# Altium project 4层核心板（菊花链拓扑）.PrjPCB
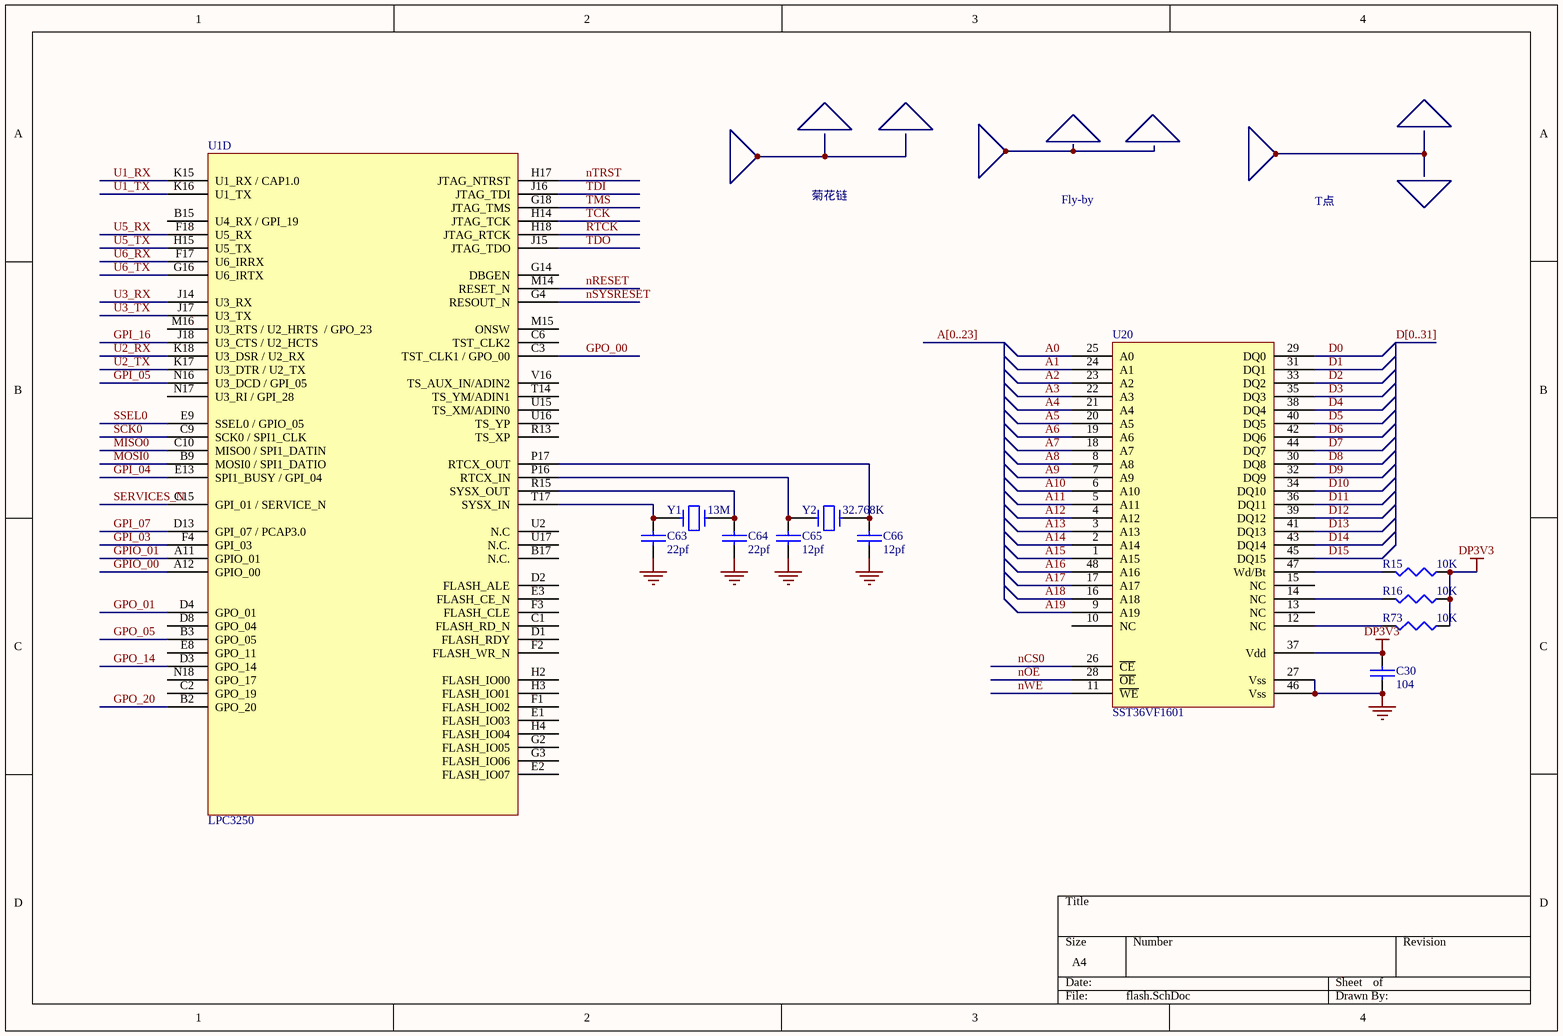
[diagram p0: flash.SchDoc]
6 sheets, 61 parts. Net scope: global (net labels, ports and power ports of the same name join across sheets).
Board file: Mian_CORE（完成版）.PcbDoc
Sheets:
  flash.SchDoc
  interface.SchDoc
  power.SchDoc
  sdram.SchDoc
  CPU.SchDoc
  EMC.SchDoc

## Sheet flash.SchDoc
size A4

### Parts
C30  104  [0603C]
C63  22pf  [0603C]
C64  22pf  [0603C]
C65  12pf  [0603C]
C66  12pf  [0603C]
R15  10K  [0603R]
R16  10K  [0603R]
R73  10K  [0603R]
U1  LPC3250  [TFBGA296]  (part D of 4)
U20  SST36VF1601  [TSOP-48]
Y1  13M  [XTAL-D]
Y2  32.768K  [XTAL-D]

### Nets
DP3V3: C30.1 R15.1 R16.1 R73.1 U20.37(Vdd)
GND: C30.2 C63.2 C64.2 C65.2 C66.2 U20.27(Vss) U20.46(Vss)
A0: U20.25(A0)
A1: U20.24(A1)
A2: U20.23(A2)
A3: U20.22(A3)
A4: U20.21(A4)
A5: U20.20(A5)
A6: U20.19(A6)
A7: U20.18(A7)
A8: U20.8(A8)
A9: U20.7(A9)
A10: U20.6(A10)
A11: U20.5(A11)
A12: U20.4(A12)
A13: U20.3(A13)
A14: U20.2(A14)
A15: U20.1(A15)
A16: U20.48(A16)
A17: U20.17(A17)
A18: U20.16(A18)
A19: U20.9(A19)
D0: U20.29(DQ0)
D1: U20.31(DQ1)
D2: U20.33(DQ2)
D3: U20.35(DQ3)
D4: U20.38(DQ4)
D5: U20.40(DQ5)
D6: U20.42(DQ6)
D7: U20.44(DQ7)
D8: U20.30(DQ8)
D9: U20.32(DQ9)
D10: U20.34(DQ10)
D11: U20.36(DQ11)
D12: U20.39(DQ12)
D13: U20.41(DQ13)
D14: U20.43(DQ14)
D15: U20.45(DQ15)
GPI_03: U1.F4(GPI_03)
GPI_04: U1.E13(SPI1_BUSY_/_GPI_04)
GPI_05: U1.N16(U3_DCD_/_GPI_05)
GPI_07: U1.D13(GPI_07_/_PCAP3.0)
GPI_16: U1.J18(U3_CTS_/_U2_HCTS)
GPIO_00: U1.A12(GPIO_00)
GPIO_01: U1.A11(GPIO_01)
GPO_00: U1.C3(TST_CLK1_/_GPO_00)
GPO_01: U1.D4(GPO_01)
GPO_05: U1.B3(GPO_05)
GPO_14: U1.D3(GPO_14)
GPO_20: U1.B2(GPO_20)
MISO0: U1.C10(MISO0_/_SPI1_DATIN)
MOSI0: U1.B9(MOSI0_/_SPI1_DATIO)
nCS0: U20.26(~{CE})
nOE: U20.28(~{OE})
nRESET: U1.M14(RESET_N)
nSYSRESET: U1.G4(RESOUT_N)
nTRST: U1.H17(JTAG_NTRST)
nWE: U20.11(~{WE})
RTCK: U1.H18(JTAG_RTCK)
SCK0: U1.C9(SCK0_/_SPI1_CLK)
SERVICES_N: U1.C15(GPI_01_/_SERVICE_N)
SSEL0: U1.E9(SSEL0_/_GPIO_05)
TCK: U1.H14(JTAG_TCK)
TDI: U1.J16(JTAG_TDI)
TDO: U1.J15(JTAG_TDO)
TMS: U1.G18(JTAG_TMS)
U1_RX: U1.K15(U1_RX_/_CAP1.0)
U1_TX: U1.K16(U1_TX)
U2_RX: U1.K18(U3_DSR_/_U2_RX)
U2_TX: U1.K17(U3_DTR_/_U2_TX)
U3_RX: U1.J14(U3_RX)
U3_TX: U1.J17(U3_TX)
U5_RX: U1.F18(U5_RX)
U5_TX: U1.H15(U5_TX)
U6_RX: U1.F17(U6_IRRX)
U6_TX: U1.G16(U6_IRTX)
NetC63_1: C63.1 U1.T17(SYSX_IN) Y1.2
NetC64_1: C64.1 U1.R15(SYSX_OUT) Y1.1
NetC65_1: C65.1 U1.P16(RTCX_IN) Y2.2
NetC66_1: C66.1 U1.P17(RTCX_OUT) Y2.1
NetR15_2: R15.2 U20.47(Wd/Bt)
NetR16_2: R16.2 U20.14(NC)
NetR73_2: R73.2 U20.12(NC)

Not connected (* = marked no-connect by the designer): U1 B15(U4_RX_/_GPI_19) B17(N.C.) C1(FLASH_RD_N) C2(GPO_19) C6(TST_CLK2) D1(FLASH_RDY) D2(FLASH_ALE) D8(GPO_04) E1(FLASH_IO03) E2(FLASH_IO07) E3(FLASH_CE_N) E8(GPO_11) F1(FLASH_IO02) F2(FLASH_WR_N) F3(FLASH_CLE) G2(FLASH_IO05) G3(FLASH_IO06) G14(DBGEN) H2(FLASH_IO00) H3(FLASH_IO01) H4(FLASH_IO04) M15(ONSW) M16(U3_RTS_/_U2_HRTS__/_GPO_23) N17(U3_RI_/_GPI_28) N18(GPO_17) R13(TS_XP) T14(TS_YM/ADIN1) U2(N.C) U15(TS_XM/ADIN0) U16(TS_YP) U17(N.C.) V16(TS_AUX_IN/ADIN2); U20 10(NC) 13(NC) 15(NC)

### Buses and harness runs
bus A[0..23]
bus D[0..31]

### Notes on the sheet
- 菊花链
- Fly-by
- T点

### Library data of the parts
C30 C63-C66 = CAP: Capacitor
R15 R16 R73 = RES
U1 = LPC3250A
Y1 Y2 = CRYSTAL

## Sheet interface.SchDoc
size A4
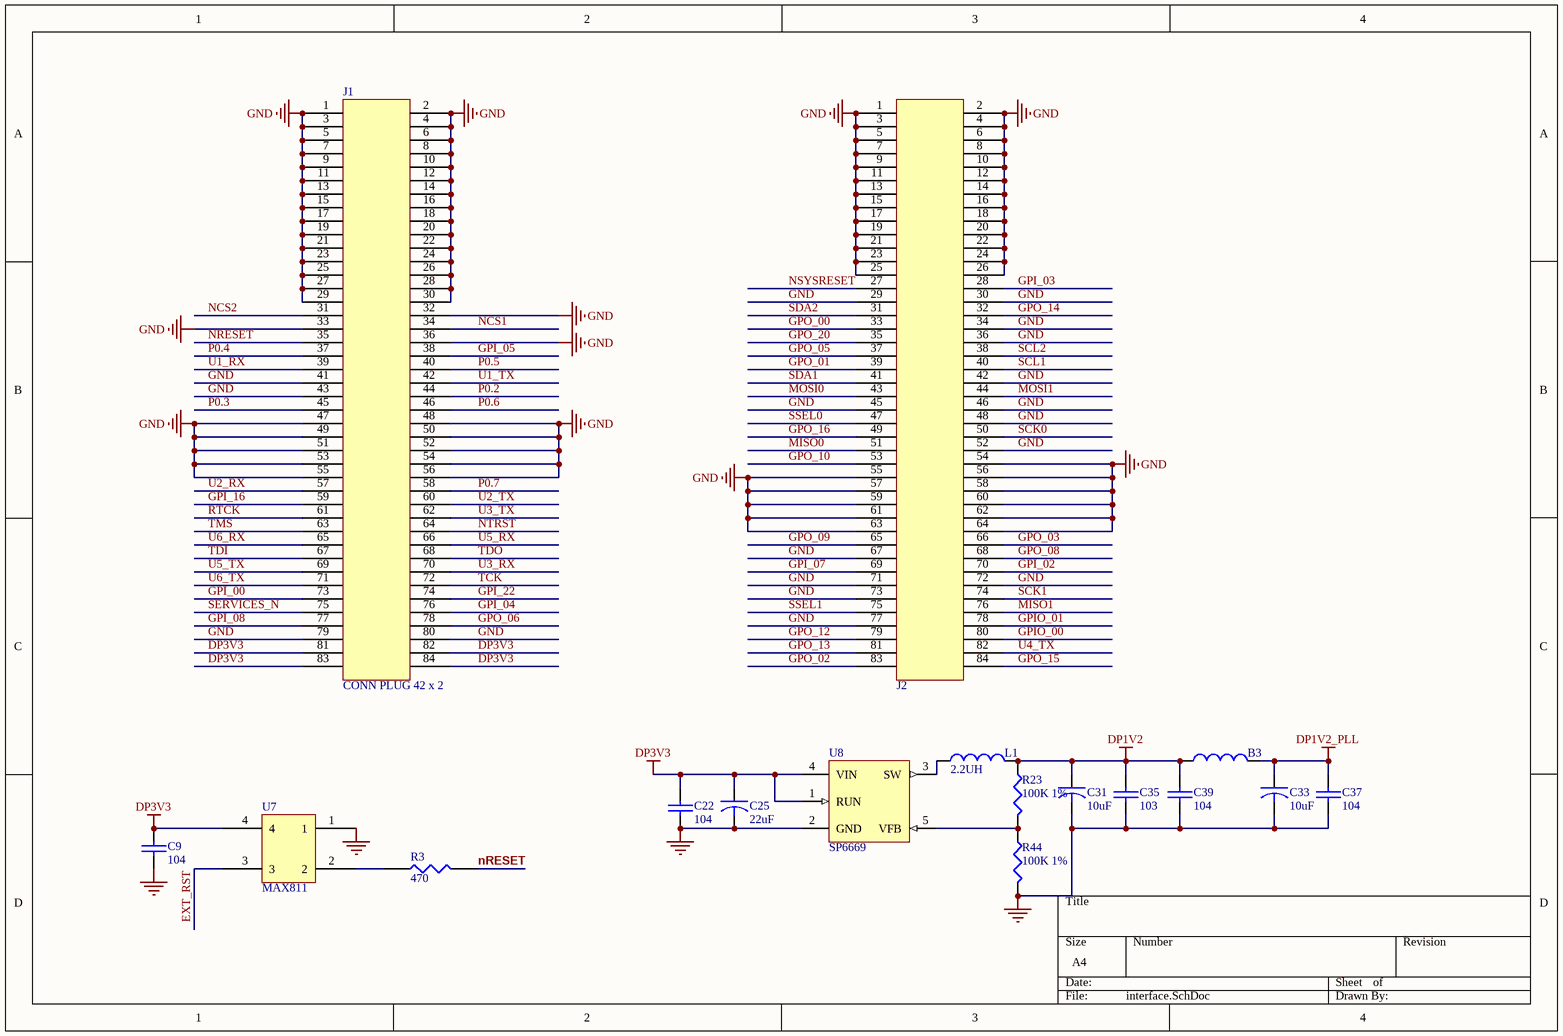
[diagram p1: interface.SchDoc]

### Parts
B3  (no value)  [0603]
C9  104  [0603C]
C22  104  [0603C]
C25  22uF  [TC-3528]
C31  10uF  [TC-3528]
C33  10uF  [TC-3528]
C35  103  [0603C]
C37  104  [0603C]
C39  104  [0603C]
J1  CONN PLUG 42 x 2  [DIP84]
J2  CONN PLUG 42 x 2  [DIP84]  (value not drawn)
L1  2.2UH  [0805]
R3  470  [0603R]
R23  100K 1%  [0603R]
R44  100K 1%  [0603R]
U7  MAX811  [MAX811]
U8  SP6669  [SOT-23-5]

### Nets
DP1V2: B3.1 C31.1 C35.2 C39.2 L1.2 R23.1
DP1V2_PLL: B3.2 C33.1 C37.2
DP3V3: C9.1 C22.2 C25.1 J1.81 J1.82 J1.83 J1.84 U7.4 U8.1(RUN) U8.4(VIN)
GND: C9.2 C22.1 C25.2 C31.2 C33.2 C35.1 C37.1 C39.1 J1.1 J1.2 J1.3 J1.4 J1.5 J1.6 J1.7 J1.8 J1.9 J1.10 J1.11 J1.12 J1.13 J1.14 J1.15 J1.16 J1.17 J1.18 J1.19 J1.20 J1.21 J1.22 J1.23 J1.24 J1.25 J1.26 J1.27 J1.28 J1.29 J1.30 J1.32 J1.33 J1.36 J1.41 J1.43 J1.47 J1.48 J1.49 J1.50 J1.51 J1.52 J1.53 J1.54 J1.55 J1.56 J1.79 J1.80 J2.1 J2.2 J2.3 J2.4 J2.5 J2.6 J2.7 J2.8 J2.9 J2.10 J2.11 J2.12 J2.13 J2.14 J2.15 J2.16 J2.17 J2.18 J2.19 J2.20 J2.21 J2.22 J2.23 J2.24 J2.25 J2.26 J2.29 J2.30 J2.34 J2.36 J2.42 J2.45 J2.46 J2.48 J2.52 J2.54 J2.55 J2.56 J2.57 J2.58 J2.59 J2.60 J2.61 J2.62 J2.63 J2.64 J2.67 J2.71 J2.72 J2.73 J2.77 R44.2 U7.1 U8.2(GND)
EXT_RST: U7.3
GPI_00: J1.73
GPI_02: J2.70
GPI_03: J2.28
GPI_04: J1.76
GPI_05: J1.38
GPI_07: J2.69
GPI_08: J1.77
GPI_16: J1.59
GPI_22: J1.74
GPIO_00: J2.80
GPIO_01: J2.78
GPO_00: J2.33
GPO_01: J2.39
GPO_02: J2.83
GPO_03: J2.66
GPO_05: J2.37
GPO_06: J1.78
GPO_08: J2.68
GPO_09: J2.65
GPO_10: J2.53
GPO_12: J2.79
GPO_13: J2.81
GPO_14: J2.32
GPO_15: J2.84
GPO_16: J2.49
GPO_20: J2.35
MISO0: J2.51
MISO1: J2.76
MOSI0: J2.43
MOSI1: J2.44
NCS1: J1.34
NCS2: J1.31
nRESET: J1.35 R3.2
nSYSRESET: J2.27
nTRST: J1.64
P0.2: J1.44
P0.3: J1.45
P0.4: J1.37
P0.5: J1.40
P0.6: J1.46
P0.7: J1.58
RTCK: J1.61
SCK0: J2.50
SCK1: J2.74
SCL1: J2.40
SCL2: J2.38
SDA1: J2.41
SDA2: J2.31
SERVICES_N: J1.75
SSEL0: J2.47
SSEL1: J2.75
TCK: J1.72
TDI: J1.67
TDO: J1.68
TMS: J1.63
U1_RX: J1.39
U1_TX: J1.42
U2_RX: J1.57
U2_TX: J1.60
U3_RX: J1.70
U3_TX: J1.62
U4_TX: J2.82
U5_RX: J1.66
U5_TX: J1.69
U6_RX: J1.65
U6_TX: J1.71
NetL1_1: L1.1 U8.3(SW)
NetR3_1: R3.1 U7.2
NetR23_2: R23.2 R44.1 U8.5(VFB)

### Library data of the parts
B3 L1 = INDUCTOR
C9 C22 C35 C37 C39 = CAP: Capacitor
C25 C31 C33 = CAPACITOR
R3 = RES1
R23 R44 = RES
U8 = SP6659

## Sheet power.SchDoc
size A4
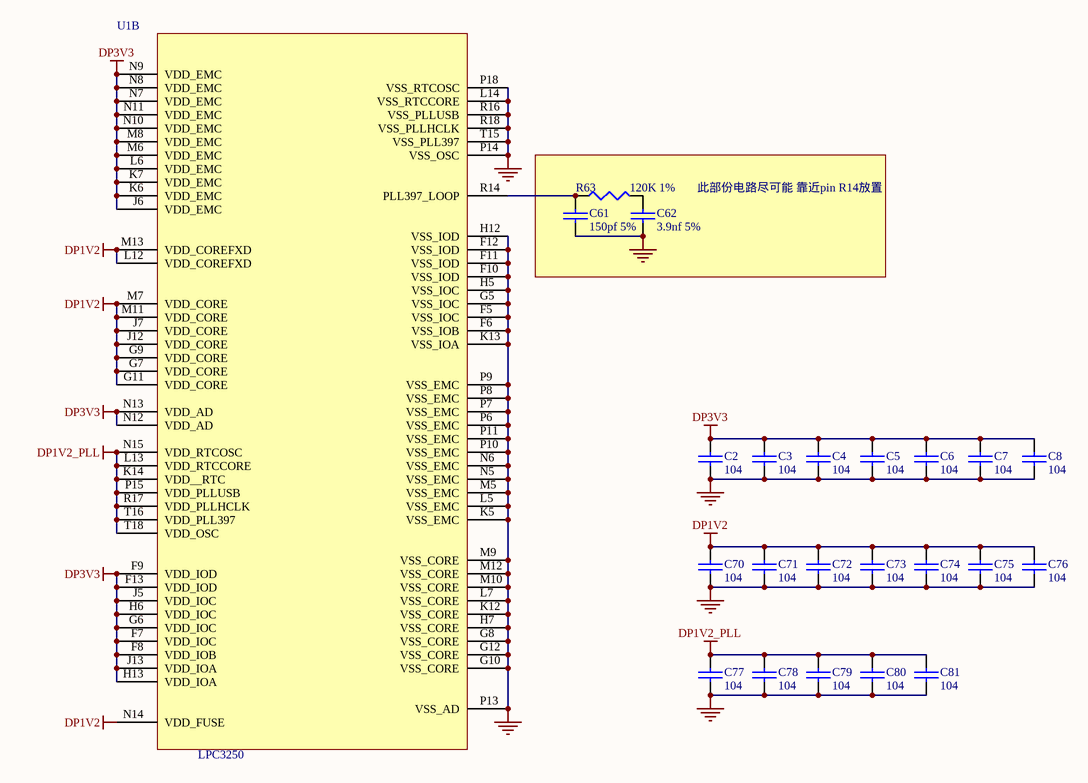
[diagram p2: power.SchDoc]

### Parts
C2  104  [0603C]
C3  104  [0603C]
C4  104  [0603C]
C5  104  [0603C]
C6  104  [0603C]
C7  104  [0603C]
C8  104  [0603C]
C61  150pf 5%  [0603C]
C62  3.9nf 5%  [0603C]
C70  104  [0603C]
C71  104  [0603C]
C72  104  [0603C]
C73  104  [0603C]
C74  104  [0603C]
C75  104  [0603C]
C76  104  [0603C]
C77  104  [0603C]
C78  104  [0603C]
C79  104  [0603C]
C80  104  [0603C]
C81  104  [0603C]
R63  120K 1%  [0603R]
U1  LPC3250  [TFBGA296]  (part B of 4)

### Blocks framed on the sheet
此部份电路尽可能 / 靠近pin R14放置: C61 C62 R63

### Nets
DP1V2: C70.1 C71.1 C72.1 C73.1 C74.1 C75.1 C76.1 U1.G7(VDD_CORE) U1.G9(VDD_CORE) U1.G11(VDD_CORE) U1.J7(VDD_CORE) U1.J12(VDD_CORE) U1.L12(VDD_COREFXD) U1.M7(VDD_CORE) U1.M11(VDD_CORE) U1.M13(VDD_COREFXD) U1.N14(VDD_FUSE)
DP1V2_PLL: C77.1 C78.1 C79.1 C80.1 C81.1 U1.K14(VDD__RTC) U1.L13(VDD_RTCCORE) U1.N15(VDD_RTCOSC) U1.P15(VDD_PLLUSB) U1.R17(VDD_PLLHCLK) U1.T16(VDD_PLL397) U1.T18(VDD_OSC)
DP3V3: C2.1 C3.1 C4.1 C5.1 C6.1 C7.1 C8.1 U1.F7(VDD_IOC) U1.F8(VDD_IOB) U1.F9(VDD_IOD) U1.F13(VDD_IOD) U1.G6(VDD_IOC) U1.H6(VDD_IOC) U1.H13(VDD_IOA) U1.J5(VDD_IOC) U1.J6(VDD_EMC) U1.J13(VDD_IOA) U1.K6(VDD_EMC) U1.K7(VDD_EMC) U1.L6(VDD_EMC) U1.M6(VDD_EMC) U1.M8(VDD_EMC) U1.N7(VDD_EMC) U1.N8(VDD_EMC) U1.N9(VDD_EMC) U1.N10(VDD_EMC) U1.N11(VDD_EMC) U1.N12(VDD_AD) U1.N13(VDD_AD)
GND: C2.2 C3.2 C4.2 C5.2 C6.2 C7.2 C8.2 C61.2 C62.2 C70.2 C71.2 C72.2 C73.2 C74.2 C75.2 C76.2 C77.2 C78.2 C79.2 C80.2 C81.2 U1.F5(VSS_IOC) U1.F6(VSS_IOB) U1.F10(VSS_IOD) U1.F11(VSS_IOD) U1.F12(VSS_IOD) U1.G5(VSS_IOC) U1.G8(VSS_CORE) U1.G10(VSS_CORE) U1.G12(VSS_CORE) U1.H5(VSS_IOC) U1.H7(VSS_CORE) U1.H12(VSS_IOD) U1.K5(VSS_EMC) U1.K12(VSS_CORE) U1.K13(VSS_IOA) U1.L5(VSS_EMC) U1.L7(VSS_CORE) U1.L14(VSS_RTCCORE) U1.M5(VSS_EMC) U1.M9(VSS_CORE) U1.M10(VSS_CORE) U1.M12(VSS_CORE) U1.N5(VSS_EMC) U1.N6(VSS_EMC) U1.P6(VSS_EMC) U1.P7(VSS_EMC) U1.P8(VSS_EMC) U1.P9(VSS_EMC) U1.P10(VSS_EMC) U1.P11(VSS_EMC) U1.P13(VSS_AD) U1.P14(VSS_OSC) U1.P18(VSS_RTCOSC) U1.R16(VSS_PLLUSB) U1.R18(VSS_PLLHCLK) U1.T15(VSS_PLL397)
NetC61_1: C61.1 R63.1 U1.R14(PLL397_LOOP)
NetC62_1: C62.1 R63.2

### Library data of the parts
C2-C8 C61 C62 C70-C81 = CAP: Capacitor
R63 = RES
U1 = LPC3250A

## Sheet sdram.SchDoc
size A4
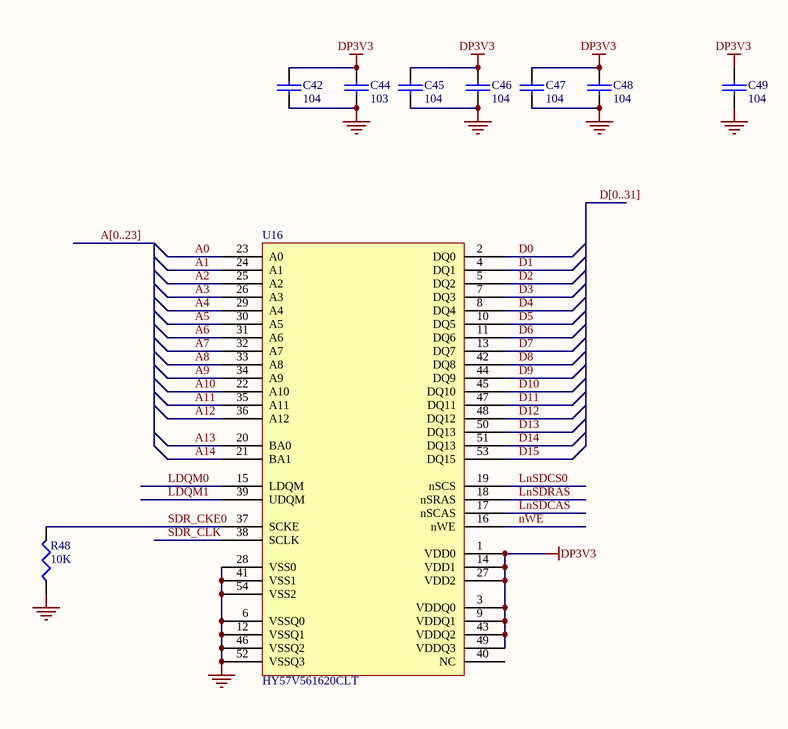
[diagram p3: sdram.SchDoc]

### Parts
C42  104  [0603C]
C44  103  [0603C]
C45  104  [0603C]
C46  104  [0603C]
C47  104  [0603C]
C48  104  [0603C]
C49  104  [0603C]
R48  10K  [0603R]
U16  HY57V561620CLT  [TSSOP-54]

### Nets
DP3V3: C42.1 C44.1 C45.1 C46.1 C47.1 C48.1 C49.1 U16.1(VDD0) U16.3(VDDQ0) U16.9(VDDQ1) U16.14(VDD1) U16.27(VDD2) U16.43(VDDQ2) U16.49(VDDQ3)
GND: C42.2 C44.2 C45.2 C46.2 C47.2 C48.2 C49.2 R48.1 U16.6(VSSQ0) U16.12(VSSQ1) U16.28(VSS0) U16.41(VSS1) U16.46(VSSQ2) U16.52(VSSQ3) U16.54(VSS2)
A0: U16.23(A0)
A1: U16.24(A1)
A2: U16.25(A2)
A3: U16.26(A3)
A4: U16.29(A4)
A5: U16.30(A5)
A6: U16.31(A6)
A7: U16.32(A7)
A8: U16.33(A8)
A9: U16.34(A9)
A10: U16.22(A10)
A11: U16.35(A11)
A12: U16.36(A12)
A13: U16.20(BA0)
A14: U16.21(BA1)
D0: U16.2(DQ0)
D1: U16.4(DQ1)
D2: U16.5(DQ2)
D3: U16.7(DQ3)
D4: U16.8(DQ4)
D5: U16.10(DQ5)
D6: U16.11(DQ6)
D7: U16.13(DQ7)
D8: U16.42(DQ8)
D9: U16.44(DQ9)
D10: U16.45(DQ10)
D11: U16.47(DQ11)
D12: U16.48(DQ12)
D13: U16.50(DQ13)
D14: U16.51(DQ13)
D15: U16.53(DQ15)
LDQM0: U16.15(LDQM)
LDQM1: U16.39(UDQM)
LnSDCAS: U16.17(nSCAS)
LnSDCS0: U16.19(nSCS)
LnSDRAS: U16.18(nSRAS)
nWE: U16.16(nWE)
SDR_CKE0: R48.2 U16.37(SCKE)
SDR_CLK: U16.38(SCLK)

Not connected (* = marked no-connect by the designer): U16 40(NC)

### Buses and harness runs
bus A[0..23]
bus D[0..31]

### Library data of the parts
C42 C44-C49 = CAP: Capacitor
R48 = RES

## Sheet CPU.SchDoc
size A4
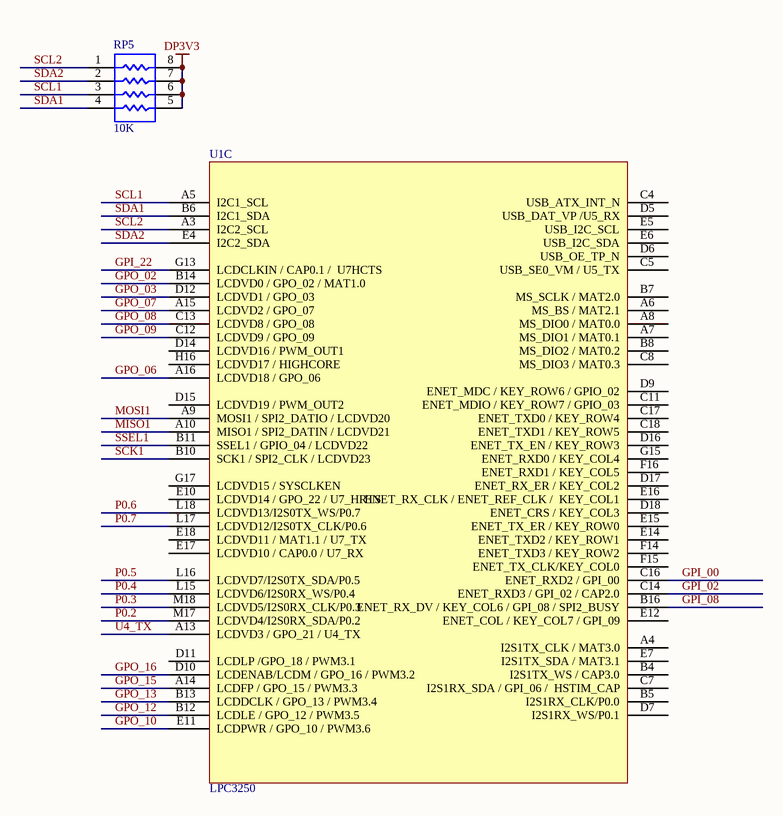
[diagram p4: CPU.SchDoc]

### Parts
RP5  10K  [PZ-4-0.8B]
U1  LPC3250  [TFBGA296]  (part C of 4)

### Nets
DP3V3: RP5.5 RP5.6 RP5.7 RP5.8
GPI_00: U1.C16(ENET_RXD2_/_GPI_00)
GPI_02: U1.C14(ENET_RXD3_/_GPI_02_/_CAP2.0)
GPI_08: U1.B16(ENET_RX_DV_/_KEY_COL6_/_GPI_08_/_SPI2_BUSY)
GPI_22: U1.G13(LCDCLKIN_/_CAP0.1_/__U7HCTS)
GPO_02: U1.B14(LCDVD0_/_GPO_02_/_MAT1.0)
GPO_03: U1.D12(LCDVD1_/_GPO_03)
GPO_06: U1.A16(LCDVD18_/_GPO_06)
GPO_07: U1.A15(LCDVD2_/_GPO_07)
GPO_08: U1.C13(LCDVD8_/_GPO_08)
GPO_09: U1.C12(LCDVD9_/_GPO_09)
GPO_10: U1.E11(LCDPWR_/_GPO_10_/_PWM3.6)
GPO_12: U1.B12(LCDLE_/_GPO_12_/_PWM3.5)
GPO_13: U1.B13(LCDDCLK_/_GPO_13_/_PWM3.4)
GPO_15: U1.A14(LCDFP_/_GPO_15_/_PWM3.3)
GPO_16: U1.D10(LCDENAB/LCDM_/_GPO_16_/_PWM3.2)
MISO1: U1.A10(MISO1_/_SPI2_DATIN_/_LCDVD21)
MOSI1: U1.A9(MOSI1_/_SPI2_DATIO_/_LCDVD20)
P0.2: U1.M17(LCDVD4/I2S0RX_SDA/P0.2)
P0.3: U1.M18(LCDVD5/I2S0RX_CLK/P0.3)
P0.4: U1.L15(LCDVD6/I2S0RX_WS/P0.4)
P0.5: U1.L16(LCDVD7/I2S0TX_SDA/P0.5)
P0.6: U1.L18(LCDVD13/I2S0TX_WS/P0.7)
P0.7: U1.L17(LCDVD12/I2S0TX_CLK/P0.6)
SCK1: U1.B10(SCK1_/_SPI2_CLK_/_LCDVD23)
SCL1: RP5.3 U1.A5(I2C1_SCL)
SCL2: RP5.1 U1.A3(I2C2_SCL)
SDA1: RP5.4 U1.B6(I2C1_SDA)
SDA2: RP5.2 U1.E4(I2C2_SDA)
SSEL1: U1.B11(SSEL1_/_GPIO_04_/_LCDVD22)
U4_TX: U1.A13(LCDVD3_/_GPO_21_/_U4_TX)

Not connected (* = marked no-connect by the designer): U1 A4(I2S1TX_CLK_/_MAT3.0) A6(MS_BS_/_MAT2.1) A7(MS_DIO1_/_MAT0.1) A8(MS_DIO0_/_MAT0.0) B4(I2S1TX_WS_/_CAP3.0) B5(I2S1RX_CLK/P0.0) B7(MS_SCLK_/_MAT2.0) B8(MS_DIO2_/_MAT0.2) C4(USB_ATX_INT_N) C5(USB_SE0_VM_/_U5_TX) C7(I2S1RX_SDA_/_GPI_06_/__HSTIM_CAP) C8(MS_DIO3_/_MAT0.3) C11(ENET_MDIO_/_KEY_ROW7_/_GPIO_03) C17(ENET_TXD0_/_KEY_ROW4) C18(ENET_TXD1_/_KEY_ROW5) D5(USB_DAT_VP_/U5_RX) D6(USB_OE_TP_N) D7(I2S1RX_WS/P0.1) D9(ENET_MDC_/_KEY_ROW6_/_GPIO_02) D11(LCDLP_/GPO_18_/_PWM3.1) D14(LCDVD16_/_PWM_OUT1) D15(LCDVD19_/_PWM_OUT2) D16(ENET_TX_EN_/_KEY_ROW3) D17(ENET_RX_ER_/_KEY_COL2) D18(ENET_CRS_/_KEY_COL3) E5(USB_I2C_SCL) E6(USB_I2C_SDA) E7(I2S1TX_SDA_/_MAT3.1) E10(LCDVD14_/_GPO_22_/_U7_HRTS) E12(ENET_COL_/_KEY_COL7_/_GPI_09) E14(ENET_TXD2_/_KEY_ROW1) E15(ENET_TX_ER_/_KEY_ROW0) E16(ENET_RX_CLK_/_ENET_REF_CLK_/__KEY_COL1) E17(LCDVD10_/_CAP0.0_/_U7_RX) E18(LCDVD11_/_MAT1.1_/_U7_TX) F14(ENET_TXD3_/_KEY_ROW2) F15(ENET_TX_CLK/KEY_COL0) F16(ENET_RXD1_/_KEY_COL5) G15(ENET_RXD0_/_KEY_COL4) G17(LCDVD15_/_SYSCLKEN) H16(LCDVD17_/_HIGHCORE)

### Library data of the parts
RP5 = RP4
U1 = LPC3250A

## Sheet EMC.SchDoc: LPC3250-EMC
size A4; DrawnBy: ZhanHL
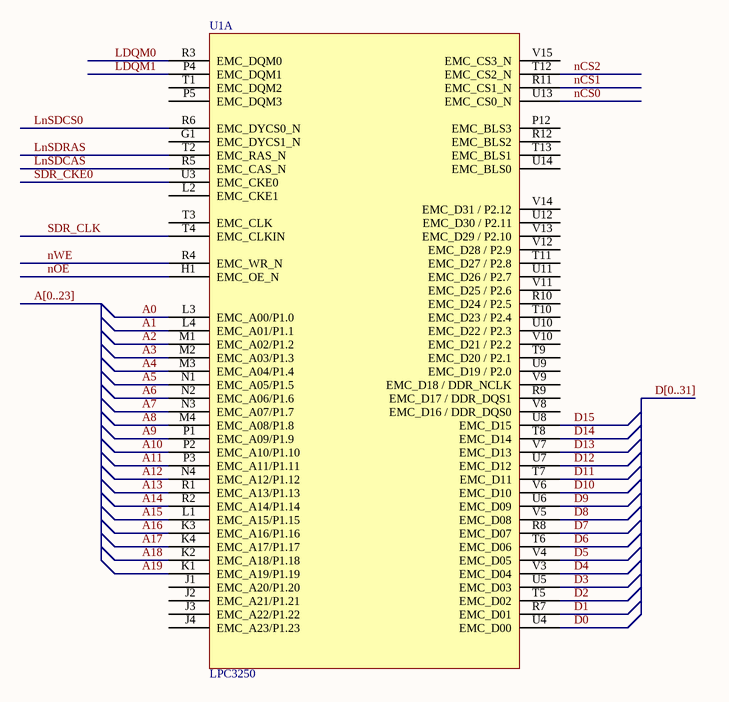
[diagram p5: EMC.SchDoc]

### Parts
U1  LPC3250  [TFBGA296]  (part A of 4)

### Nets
A0: U1.L3(EMC_A00/P1.0)
A1: U1.L4(EMC_A01/P1.1)
A2: U1.M1(EMC_A02/P1.2)
A3: U1.M2(EMC_A03/P1.3)
A4: U1.M3(EMC_A04/P1.4)
A5: U1.N1(EMC_A05/P1.5)
A6: U1.N2(EMC_A06/P1.6)
A7: U1.N3(EMC_A07/P1.7)
A8: U1.M4(EMC_A08/P1.8)
A9: U1.P1(EMC_A09/P1.9)
A10: U1.P2(EMC_A10/P1.10)
A11: U1.P3(EMC_A11/P1.11)
A12: U1.N4(EMC_A12/P1.12)
A13: U1.R1(EMC_A13/P1.13)
A14: U1.R2(EMC_A14/P1.14)
A15: U1.L1(EMC_A15/P1.15)
A16: U1.K3(EMC_A16/P1.16)
A17: U1.K4(EMC_A17/P1.17)
A18: U1.K2(EMC_A18/P1.18)
A19: U1.K1(EMC_A19/P1.19)
D0: U1.U4(EMC_D00)
D1: U1.R7(EMC_D01)
D2: U1.T5(EMC_D02)
D3: U1.U5(EMC_D03)
D4: U1.V3(EMC_D04)
D5: U1.V4(EMC_D05)
D6: U1.T6(EMC_D06)
D7: U1.R8(EMC_D07)
D8: U1.V5(EMC_D08)
D9: U1.U6(EMC_D09)
D10: U1.V6(EMC_D10)
D11: U1.T7(EMC_D11)
D12: U1.U7(EMC_D12)
D13: U1.V7(EMC_D13)
D14: U1.T8(EMC_D14)
D15: U1.U8(EMC_D15)
LDQM0: U1.R3(EMC_DQM0)
LDQM1: U1.P4(EMC_DQM1)
LnSDCAS: U1.R5(EMC_CAS_N)
LnSDCS0: U1.R6(EMC_DYCS0_N)
LnSDRAS: U1.T2(EMC_RAS_N)
nCS0: U1.U13(EMC_CS0_N)
NCS1: U1.R11(EMC_CS1_N)
NCS2: U1.T12(EMC_CS2_N)
nOE: U1.H1(EMC_OE_N)
nWE: U1.R4(EMC_WR_N)
SDR_CKE0: U1.U3(EMC_CKE0)
SDR_CLK: U1.T4(EMC_CLKIN)

Not connected (* = marked no-connect by the designer): U1 G1(EMC_DYCS1_N) J1(EMC_A20/P1.20) J2(EMC_A21/P1.21) J3(EMC_A22/P1.22) J4(EMC_A23/P1.23) L2(EMC_CKE1) P5(EMC_DQM3) P12(EMC_BLS3) R9(EMC_D17_/_DDR_DQS1) R10(EMC_D24_/_P2.5) R12(EMC_BLS2) T1(EMC_DQM2) T3(EMC_CLK) T9(EMC_D20_/_P2.1) T10(EMC_D23_/_P2.4) T11(EMC_D27_/_P2.8) T13(EMC_BLS1) U9(EMC_D19_/_P2.0) U10(EMC_D22_/_P2.3) U11(EMC_D26_/_P2.7) U12(EMC_D30_/_P2.11) U14(EMC_BLS0) V8(EMC_D16_/_DDR_DQS0) V9(EMC_D18_/_DDR_NCLK) V10(EMC_D21_/_P2.2) V11(EMC_D25_/_P2.6) V12(EMC_D28_/_P2.9) V13(EMC_D29_/_P2.10) V14(EMC_D31_/_P2.12) V15(EMC_CS3_N)

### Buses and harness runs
bus A[0..23]
bus D[0..31]

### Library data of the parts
U1 = LPC3250A

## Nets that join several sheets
DP1V2: interface (6 pins), power (17 pins)
DP1V2_PLL: interface (B3.2 C33.1 C37.2), power (12 pins)
DP3V3: flash (5 pins), interface (10 pins), power (29 pins), sdram (14 pins), CPU (RP5.5 RP5.6 RP5.7 RP5.8)
GND: flash (7 pins), interface (109 pins), power (57 pins), sdram (15 pins)
A0: flash (U20.25), sdram (U16.23), EMC (U1.L3)
A1: flash (U20.24), sdram (U16.24), EMC (U1.L4)
A2: flash (U20.23), sdram (U16.25), EMC (U1.M1)
A3: flash (U20.22), sdram (U16.26), EMC (U1.M2)
A4: flash (U20.21), sdram (U16.29), EMC (U1.M3)
A5: flash (U20.20), sdram (U16.30), EMC (U1.N1)
A6: flash (U20.19), sdram (U16.31), EMC (U1.N2)
A7: flash (U20.18), sdram (U16.32), EMC (U1.N3)
A8: flash (U20.8), sdram (U16.33), EMC (U1.M4)
A9: flash (U20.7), sdram (U16.34), EMC (U1.P1)
A10: flash (U20.6), sdram (U16.22), EMC (U1.P2)
A11: flash (U20.5), sdram (U16.35), EMC (U1.P3)
A12: flash (U20.4), sdram (U16.36), EMC (U1.N4)
A13: flash (U20.3), sdram (U16.20), EMC (U1.R1)
A14: flash (U20.2), sdram (U16.21), EMC (U1.R2)
A15: flash (U20.1), EMC (U1.L1)
A16: flash (U20.48), EMC (U1.K3)
A17: flash (U20.17), EMC (U1.K4)
A18: flash (U20.16), EMC (U1.K2)
A19: flash (U20.9), EMC (U1.K1)
D0: flash (U20.29), sdram (U16.2), EMC (U1.U4)
D1: flash (U20.31), sdram (U16.4), EMC (U1.R7)
D2: flash (U20.33), sdram (U16.5), EMC (U1.T5)
D3: flash (U20.35), sdram (U16.7), EMC (U1.U5)
D4: flash (U20.38), sdram (U16.8), EMC (U1.V3)
D5: flash (U20.40), sdram (U16.10), EMC (U1.V4)
D6: flash (U20.42), sdram (U16.11), EMC (U1.T6)
D7: flash (U20.44), sdram (U16.13), EMC (U1.R8)
D8: flash (U20.30), sdram (U16.42), EMC (U1.V5)
D9: flash (U20.32), sdram (U16.44), EMC (U1.U6)
D10: flash (U20.34), sdram (U16.45), EMC (U1.V6)
D11: flash (U20.36), sdram (U16.47), EMC (U1.T7)
D12: flash (U20.39), sdram (U16.48), EMC (U1.U7)
D13: flash (U20.41), sdram (U16.50), EMC (U1.V7)
D14: flash (U20.43), sdram (U16.51), EMC (U1.T8)
D15: flash (U20.45), sdram (U16.53), EMC (U1.U8)
GPI_00: interface (J1.73), CPU (U1.C16)
GPI_02: interface (J2.70), CPU (U1.C14)
GPI_03: flash (U1.F4), interface (J2.28)
GPI_04: flash (U1.E13), interface (J1.76)
GPI_05: flash (U1.N16), interface (J1.38)
GPI_07: flash (U1.D13), interface (J2.69)
GPI_08: interface (J1.77), CPU (U1.B16)
GPI_16: flash (U1.J18), interface (J1.59)
GPI_22: interface (J1.74), CPU (U1.G13)
GPIO_00: flash (U1.A12), interface (J2.80)
GPIO_01: flash (U1.A11), interface (J2.78)
GPO_00: flash (U1.C3), interface (J2.33)
GPO_01: flash (U1.D4), interface (J2.39)
GPO_02: interface (J2.83), CPU (U1.B14)
GPO_03: interface (J2.66), CPU (U1.D12)
GPO_05: flash (U1.B3), interface (J2.37)
GPO_06: interface (J1.78), CPU (U1.A16)
GPO_08: interface (J2.68), CPU (U1.C13)
GPO_09: interface (J2.65), CPU (U1.C12)
GPO_10: interface (J2.53), CPU (U1.E11)
GPO_12: interface (J2.79), CPU (U1.B12)
GPO_13: interface (J2.81), CPU (U1.B13)
GPO_14: flash (U1.D3), interface (J2.32)
GPO_15: interface (J2.84), CPU (U1.A14)
GPO_16: interface (J2.49), CPU (U1.D10)
GPO_20: flash (U1.B2), interface (J2.35)
LDQM0: sdram (U16.15), EMC (U1.R3)
LDQM1: sdram (U16.39), EMC (U1.P4)
LnSDCAS: sdram (U16.17), EMC (U1.R5)
LnSDCS0: sdram (U16.19), EMC (U1.R6)
LnSDRAS: sdram (U16.18), EMC (U1.T2)
MISO0: flash (U1.C10), interface (J2.51)
MISO1: interface (J2.76), CPU (U1.A10)
MOSI0: flash (U1.B9), interface (J2.43)
MOSI1: interface (J2.44), CPU (U1.A9)
nCS0: flash (U20.26), EMC (U1.U13)
NCS1: interface (J1.34), EMC (U1.R11)
NCS2: interface (J1.31), EMC (U1.T12)
nOE: flash (U20.28), EMC (U1.H1)
nRESET: flash (U1.M14), interface (J1.35 R3.2)
nSYSRESET: flash (U1.G4), interface (J2.27)
nTRST: flash (U1.H17), interface (J1.64)
nWE: flash (U20.11), sdram (U16.16), EMC (U1.R4)
P0.2: interface (J1.44), CPU (U1.M17)
P0.3: interface (J1.45), CPU (U1.M18)
P0.4: interface (J1.37), CPU (U1.L15)
P0.5: interface (J1.40), CPU (U1.L16)
P0.6: interface (J1.46), CPU (U1.L18)
P0.7: interface (J1.58), CPU (U1.L17)
RTCK: flash (U1.H18), interface (J1.61)
SCK0: flash (U1.C9), interface (J2.50)
SCK1: interface (J2.74), CPU (U1.B10)
SCL1: interface (J2.40), CPU (RP5.3 U1.A5)
SCL2: interface (J2.38), CPU (RP5.1 U1.A3)
SDA1: interface (J2.41), CPU (RP5.4 U1.B6)
SDA2: interface (J2.31), CPU (RP5.2 U1.E4)
SDR_CKE0: sdram (R48.2 U16.37), EMC (U1.U3)
SDR_CLK: sdram (U16.38), EMC (U1.T4)
SERVICES_N: flash (U1.C15), interface (J1.75)
SSEL0: flash (U1.E9), interface (J2.47)
SSEL1: interface (J2.75), CPU (U1.B11)
TCK: flash (U1.H14), interface (J1.72)
TDI: flash (U1.J16), interface (J1.67)
TDO: flash (U1.J15), interface (J1.68)
TMS: flash (U1.G18), interface (J1.63)
U1_RX: flash (U1.K15), interface (J1.39)
U1_TX: flash (U1.K16), interface (J1.42)
U2_RX: flash (U1.K18), interface (J1.57)
U2_TX: flash (U1.K17), interface (J1.60)
U3_RX: flash (U1.J14), interface (J1.70)
U3_TX: flash (U1.J17), interface (J1.62)
U4_TX: interface (J2.82), CPU (U1.A13)
U5_RX: flash (U1.F18), interface (J1.66)
U5_TX: flash (U1.H15), interface (J1.69)
U6_RX: flash (U1.F17), interface (J1.65)
U6_TX: flash (U1.G16), interface (J1.71)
